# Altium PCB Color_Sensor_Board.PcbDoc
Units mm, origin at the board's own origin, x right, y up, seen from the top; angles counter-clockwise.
Board outline 30 x 30 mm, 2 copper layers (Top Layer, Bottom Layer), stack 1.586 mm thick; 46 components, 24 nets, 122 pads, 55 vias.
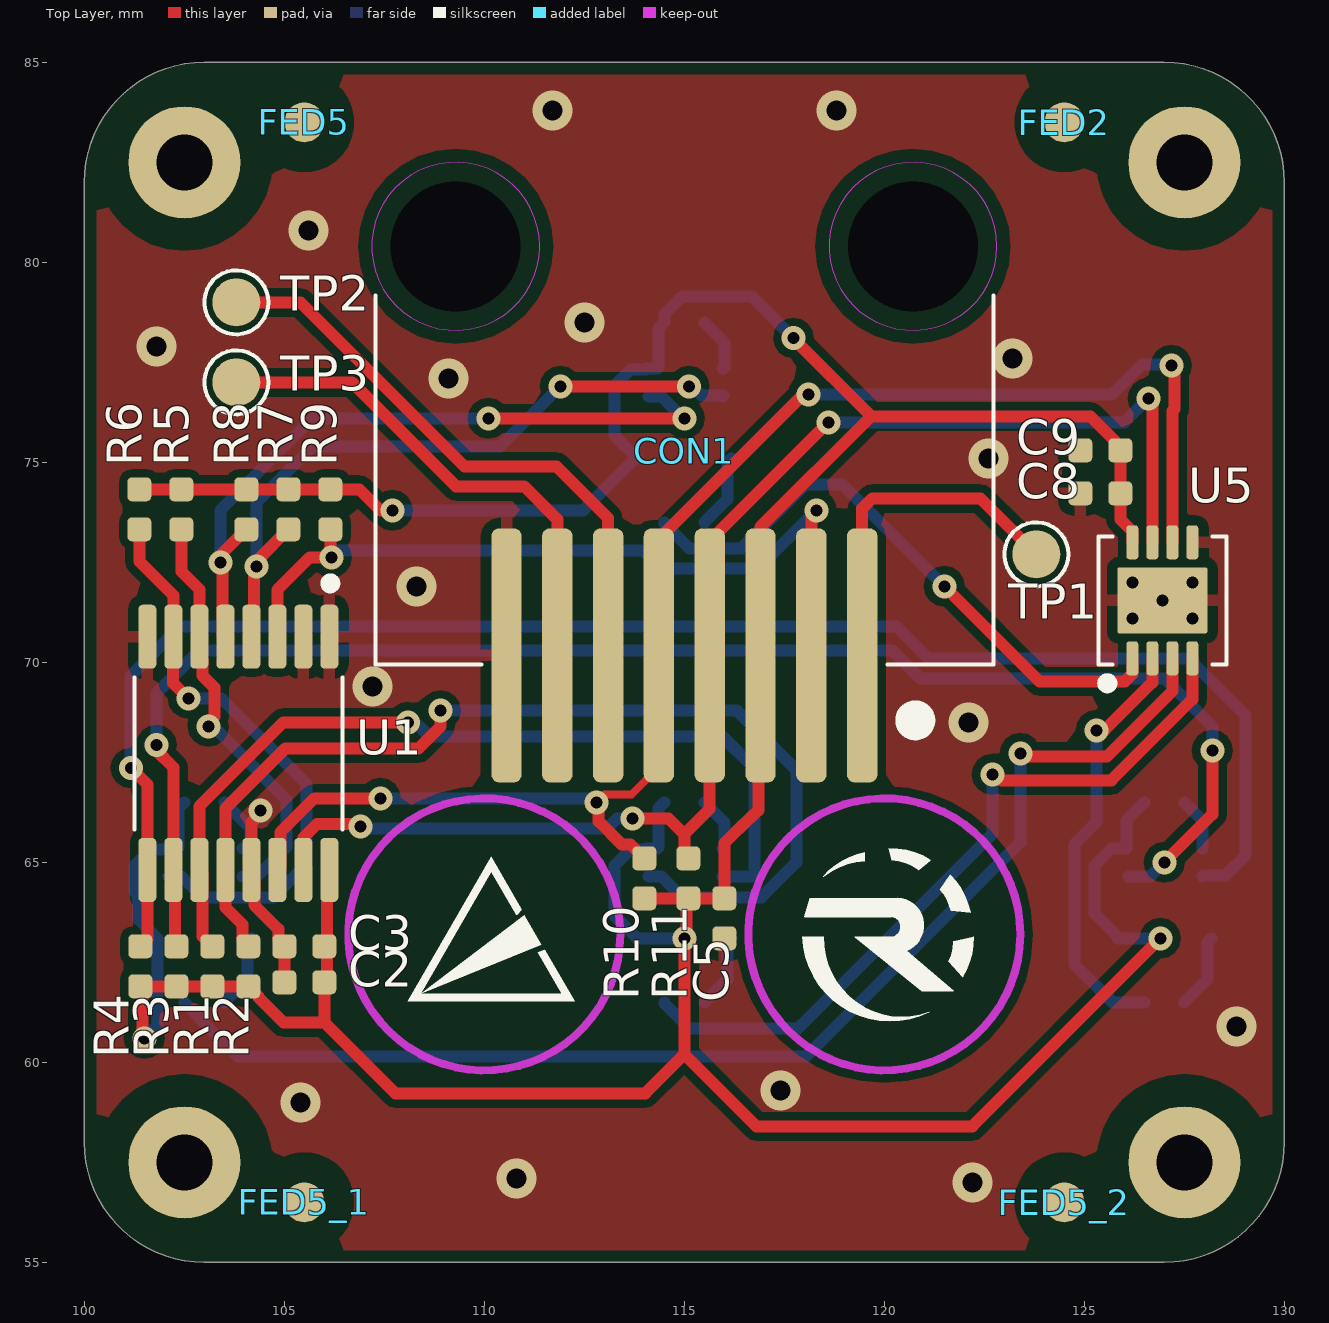
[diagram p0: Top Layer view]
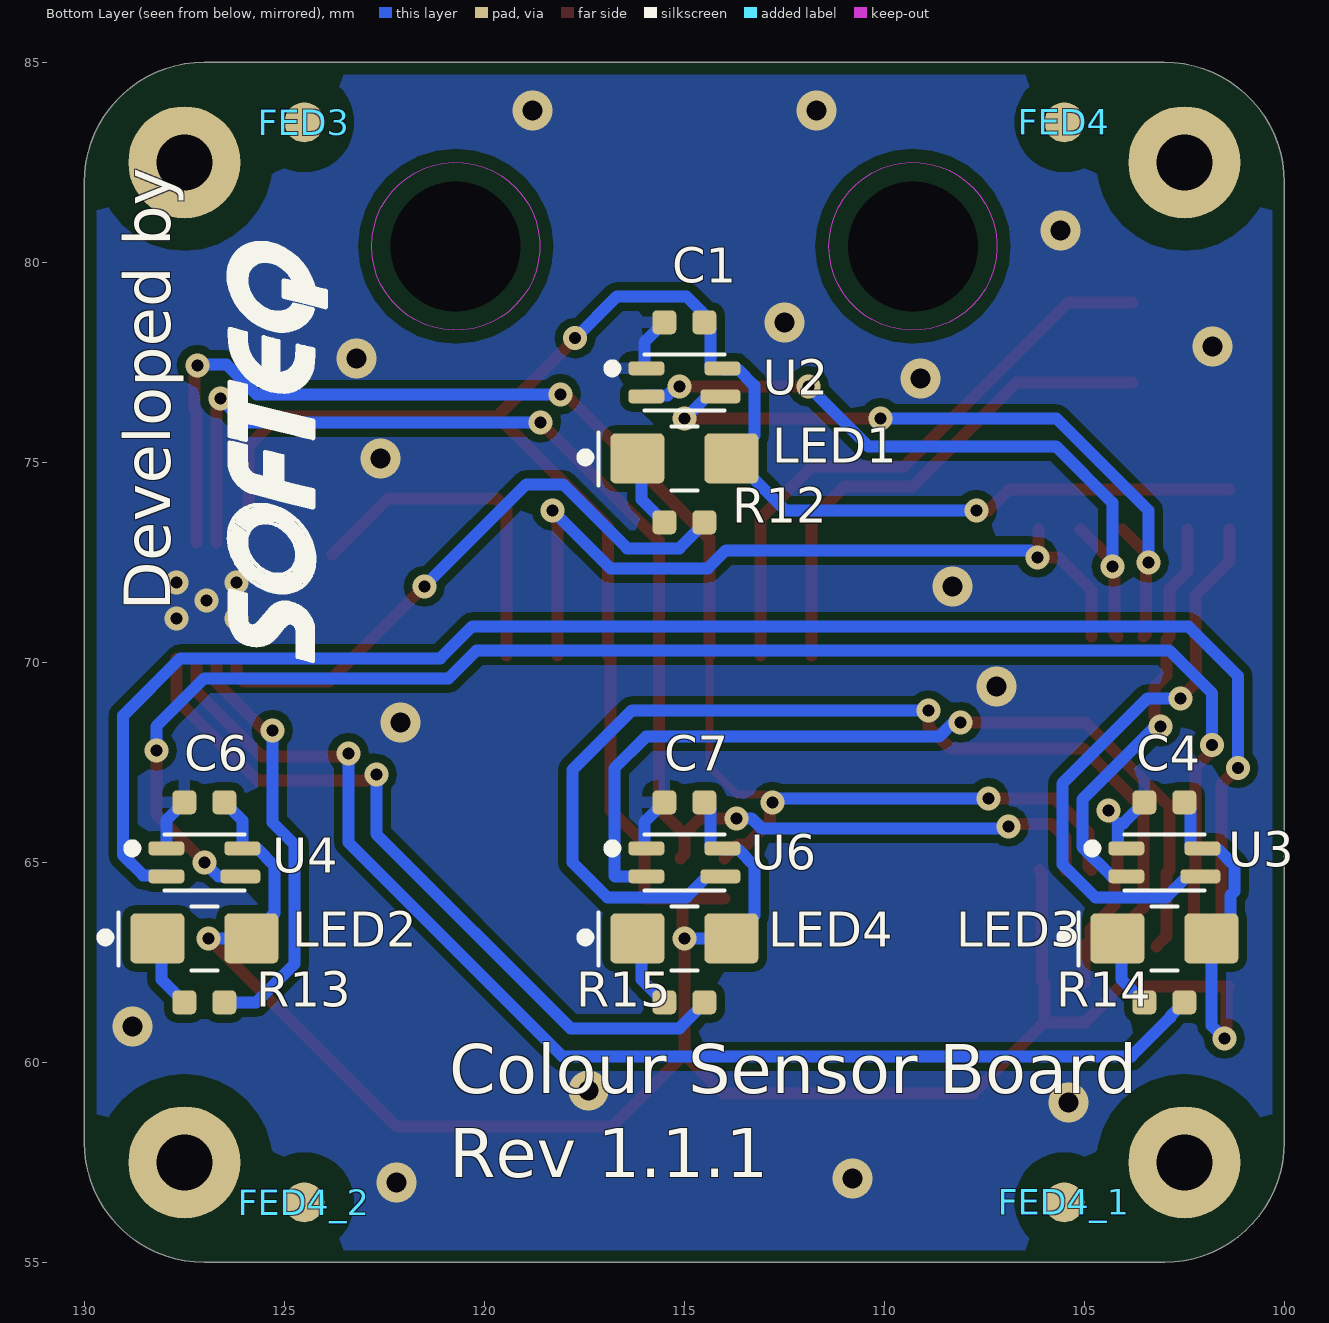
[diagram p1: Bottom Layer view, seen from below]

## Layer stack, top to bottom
Top Solder: solder mask 0.0254, SM-002, Dk 4
Top Layer: signal copper 0.043
Dielectric 1: dielectric 1.5, FR-4, Dk 4.8
Bottom Layer: signal copper 0.043
Bottom Solder: solder mask 0.0254, SM-002, Dk 4

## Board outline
100,58 100,82 cw(c103,82) 103,85 127,85 cw(c127,82) 130,82 130,58 cw(c127,58) 127,55 103,55 cw(c103,58)

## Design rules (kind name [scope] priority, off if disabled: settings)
BoardOutlineClearance [All] p1: gap=0.3 ignorepadtopadclearanceinfootprint=FALSE
Clearance [All] p1: gap=0.2 ignorepadtopadclearanceinfootprint=FALSE except(0.8: THPad-Fill THPad-Poly THPad-Region)
HoleSize [All] p1: absolutevalues=TRUE maxlimit=5 minlimit=0.025 maxpercent=80.000 minpercent=20.000
MinimumSolderMaskSliver [All] p1: minsoldermaskwidth=0.1
PolygonConnect [All] p1: thpad.connectstyle=Relief thpad.reliefconductorwidth=0.3 thpad.reliefentries=4 thpad.polygonreliefangle="90 Angle" thpad.airgapwidth=0.25 smdpad.connectstyle=Relief smdpad.reliefconductorwidth=0.3 smdpad.reliefentries=4 smdpad.polygonreliefangle="90 Angle" smdpad.airgapwidth=0.25 via.connectstyle=Direct via.reliefconductorwidth=0.254 via.reliefentries=4 via.polygonreliefangle="90 Angle" via.airgapwidth=0.254
RoutingVias [All] p1: holewidth=0.3 width=0.6 viastyle="Through Hole" minholewidth=0.3 minwidth=0.6 maxholewidth=0.711 maxwidth=1.27
SilkToSilkClearance [All] p1: silktosilkclearance=0
SilkToSolderMaskClearance [IsPad] p1: minsilkscreentomaskgap=0.1 clearancetoexposedcopper=TRUE
SolderMaskExpansion [All] p1: expansion=0.102
Width [All] p1: maxlimit=2 minlimit=0.2 preferedwidth=0.3
26 further rules are at their usual default settings.

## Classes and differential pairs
component class 1_Circuit: C1 C2 C3 C4 C5 C6 C7 C8 C9 CON1 LED1 LED2 LED3 LED4 R1 R2 R3 R4 R5 R6 R7 R8 R9 R10 R11 R12 R13 R14 R15 TP1 TP2 TP3 U1 U2 U3 U4 U5 U6

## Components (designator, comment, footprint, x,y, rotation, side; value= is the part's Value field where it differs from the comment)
C1 "CC0402KRX7R7BB104" C_0402 115,78.5 r180 bottom value=100n
C2 "CC0402KRX5R7BB105" C_0402 105.5,62 r0 top value=1u
C3 "CC0402KRX7R7BB104" C_0402 105.5,62.9 r0 top value=100n
C4 "CC0402KRX7R7BB104" C_0402 103,66.5 r180 bottom value=100n
C5 "C0402C106M9PAC7867" C_0402 116,63.6 r90 top value=10u
C6 "CC0402KRX7R7BB104" C_0402 127,66.5 r180 bottom value=100n
C7 "CC0402KRX7R7BB104" C_0402 115,66.5 r180 bottom value=100n
C8 "CC0402KRX5R7BB105" C_0402 125.4,74.225 r0 top value=1u
C9 "CC0402KRX7R7BB104" C_0402 125.4,75.3 r0 top value=100n
CON1 "0955016890" MOLEX_955016890 115,70.175 r180 top locked
FED2 "FEDUCIAL_1MM" FEDUCIAL 124.5,83.5 r0 top
FED3 "FEDUCIAL_1MM" FEDUCIAL 124.5,83.5 r180 bottom
FED4 "FEDUCIAL_1MM" FEDUCIAL 105.5,83.5 r180 bottom
FED4_1 "FEDUCIAL_1MM" FEDUCIAL 105.5,56.5 r180 bottom
FED4_2 "FEDUCIAL_1MM" FEDUCIAL 124.5,56.5 r180 bottom
FED5 "FEDUCIAL_1MM" FEDUCIAL 105.5,83.5 r0 top
FED5_1 "FEDUCIAL_1MM" FEDUCIAL 105.5,56.5 r0 top
FED5_2 "FEDUCIAL_1MM" FEDUCIAL 124.5,56.5 r0 top
LED1 "LTW-M140SZS40" Lite-On_LTW-M140SZS40 115,75.1 r180 bottom
LED2 "LTW-M140SZS40" Lite-On_LTW-M140SZS40 127,63.1 r180 bottom
LED3 "LTW-M140SZS40" Lite-On_LTW-M140SZS40 103,63.1 r180 bottom
LED4 "LTW-M140SZS40" Lite-On_LTW-M140SZS40 115,63.1 r180 bottom
R1 "RC0402FR-074K7L" R_0402 103.2,62.4 r270 top value=4.7K
R2 "RC0402FR-074K7L" R_0402 104.1,62.4 r270 top value=4.7K
R3 "RC0402FR-074K7L" R_0402 101.4,62.4 r270 top value=4.7K
R4 "RC0402FR-074K7L" R_0402 102.3,62.4 r270 top value=4.7K
R5 "RC0402FR-074K7L" R_0402 102.425,73.825 r90 top value=4.7K
R6 "RC0402FR-074K7L" R_0402 101.375,73.825 r90 top value=4.7K
R7 "RC0402FR-074K7L" R_0402 105.1,73.825 r90 top value=4.7K
R8 "RC0402FR-074K7L" R_0402 104.05,73.825 r90 top value=4.7K
R9 "RC0402FR-07100KL" R_0402 106.15,73.825 r90 top value=100K
R10 "RC0402FR-074K7L" R_0402 114,64.6 r270 top value=4.7K
R11 "RC0402FR-074K7L" R_0402 115.1,64.6 r270 top value=4.7K
R12 "RC0402FR-0715RL" R_0402 115,73.5 r0 bottom value=15
R13 "RC0402FR-0715RL" R_0402 127,61.5 r0 bottom value=15
R14 "RC0402FR-0715RL" R_0402 103,61.5 r0 bottom value=15
R15 "RC0402FR-0715RL" R_0402 115,61.5 r0 bottom value=15
TP1 "SolderPoint_1.2" SSP_1.2 123.8,72.7 r0 top
TP2 "SolderPoint_1.2" SSP_1.2 103.8,79 r90 top
TP3 "SolderPoint_1.2" SSP_1.2 103.8,77 r90 top
U1 "PCA9546APW" TSSOP-16[8-8]_0.45_0.65_4.4x5x1.1 103.85,67.725 r270 top
U2 "VEML3328" Vishay_VEML3328 115,77 r180 bottom
U3 "VEML3328" Vishay_VEML3328 103,65 r180 bottom
U4 "VEML3328" Vishay_VEML3328 127,65 r180 bottom locked
U5 "PCA9633TK,118" SON-8[4-4]_0.3_0.5_3x3x0.8_EP[1.65x2.25] 126.95,71.55 r90 top
U6 "VEML3328" Vishay_VEML3328 115,65 r180 bottom locked

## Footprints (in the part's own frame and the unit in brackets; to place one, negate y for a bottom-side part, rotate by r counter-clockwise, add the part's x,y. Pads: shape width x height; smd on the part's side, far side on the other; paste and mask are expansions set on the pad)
C_0402 [mm]
  rrect40% 0.6x0.6 smd paste-0.025 mask+0.05: 1(-0.5,0) 2(0.5,0)
  body extent -0.5,-0.25 0.5,0.25, height 0.55
FEDUCIAL [mm]
  round 1 smd paste-1 mask+0.5: FED(0,0)
  Top Layer pour cut-out: 0,1.25 0.478,1.155 0.884,0.884 1.155,0.478 1.25,0 1.25,0 1.155,-0.478 0.884,-0.884 0.478,-1.155 0,-1.25 0,-1.25 -0.478,-1.155 -0.884,-0.884 -1.155,-0.478 -1.25,0 -1.25,0 -1.155,0.478 -0.884,0.884 -0.478,1.155 0,1.25
Lite-On_LTW-M140SZS40 [mm]
  rrect20% 1.35x1.25 smd paste-0.025 mask+0.05: A(1.175,0) C(-1.175,0)
  silkscreen extent -2.57,-0.8 0.32,0.8, body extent -1.5,-0.7 1.5,0.7, height 1.2
MOLEX_955016890 [mm]
  rrect50% 0.76x6.35 smd paste-0.025 mask+0.05: 1(-4.445,0) 2(-3.175,0) 3(-1.905,0) 4(-0.635,0) 5(0.635,0) 6(1.905,0) 7(3.175,0) 8(4.445,0)
  round 0 hole 3.25 unplated mask+0.3: SH(-5.715,-10.225) SH(5.715,-10.225)
  Keep-Out Layer circle w0.025: c5.715,-10.225 r2.1
  Keep-Out Layer circle w0.025: c-5.715,-10.225 r2.1
  silkscreen extent -7.73,-9 7.73,1.87, body extent -7.62,-18.02 7.62,2.53, height 11.5
R_0402 [mm]
  rrect40% 0.6x0.6 smd paste-0.025 mask+0.05: 1(-0.5,0) 2(0.5,0)
  body extent -0.57,-0.27 0.58,0.28, height 0.4
SON-8[4-4]_0.3_0.5_3x3x0.8_EP[1.65x2.25] [mm] "SON, 8-Leads, Body 3.00x3.00mm, Pitch 0.50mm, IPC Medium Density"
  rrect50% 0.85x0.3 smd paste-0.025 mask+0.05: 1(-1.45,0.75) 2(-1.45,0.25) 3(-1.45,-0.25) 4(-1.45,-0.75) 5(1.45,-0.75) 6(1.45,-0.25) 7(1.45,0.25) 8(1.45,0.75)
  rrect5% 1.65x2.25 smd paste-2 mask+0.05: EP(0,0)
  silkscreen extent -2.33,-1.6 1.6,1.62, body extent -1.5,-1.5 1.5,1.5, height 1
SSP_1.2 [mm]
  round 1.2 smd paste-1.5 mask+0.05: 1(0,0)
  silkscreen extent -0.8,-0.8 0.8,0.8
TSSOP-16[8-8]_0.45_0.65_4.4x5x1.1 [mm]
  rrect49% 1.6x0.45 smd paste-0.025 mask+0.05: 1(-2.915,2.275) 2(-2.915,1.625) 3(-2.915,0.975) 4(-2.915,0.325) 5(-2.915,-0.325) 6(-2.915,-0.975) 7(-2.915,-1.625) 8(-2.915,-2.275) 9(2.915,-2.275) 10(2.915,-1.625) 11(2.915,-0.975) 12(2.915,-0.325) 13(2.915,0.325) 14(2.915,0.975) 15(2.915,1.625) 16(2.915,2.275)
  silkscreen extent -4.37,-2.6 1.9,2.6, body extent -3.2,-2.5 3.2,2.5, height 1.1
Vishay_VEML3328 [mm]
  rrect50% 0.9x0.35 smd paste-0.025 mask+0.05: 1(-0.95,0.35) 2(-0.95,-0.35) 4(0.95,0.35)
  rrect50% 1x0.35 smd paste-0.025 mask+0.05: 3(0.9,-0.35)
  silkscreen extent -1.9,-0.7 1,0.7, body extent -1,-0.62 1,0.63, height 1.01

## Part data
C1 C3 C4 C6 C7 C9: "Capacitor, 100nF, 16V, X7R, 10%, -55/+125,0402", Manufacturer=Yageo
C2 C8: "Capacitor, 1uF, 16V, X5R, 10%, -55/+85, 0402", Manufacturer=Yageo
C5: "Capacitor, 10uF, 6.3V, 20%, X5R, -55/+85 0402", Manufacturer=Kemet
CON1: "Conn, RJ-45, Unshielded, P-1.27mm, RA, -40/+85, SMD", Manufacturer=Molex
FED2 FED3 FED4 FED4_1 FED4_2 FED5 FED5_1 FED5_2: Manufacturer=-
LED1 LED2 LED3 LED4: "Diode, LED, White, 20mA, 3.2V, -30/+85, 3.0x1.4x1.2mm", Manufacturer=Lite-On
R1 R2 R3 R4 R5 R6 R7 R8 R10 R11: "Resistor, 4.7K, 1%, 0.063W, -55/+155, 0402", Manufacturer=Yageo
R9: "Resistor, 100K, 1%, 0.063W, -55/+155, 0402", Manufacturer=Yageo
R12 R13 R14 R15: "Resistor, 15, 1%, 0.0625W, -55/+155, 0402", Manufacturer=Yageo
TP1 TP2 TP3: library part SolderPoint_SMD_1.2, "Solder Point, 1.2mm, SMD"
U1: "IC, I2C/SMBus Switch, 4Ch, 400kHz, -40/+85, TSSOP-16", Manufacturer=NXP
U2 U3 U4 U6: "IC, Color Sensor, RGBCIR, I2C/SMBus, 2.6-3.6V, -40/+85, SMD", Manufacturer=Vishay
U5: "IC, LED Driver, 4Ch, 2.3-5.5V, 25mA/Ch, 100mAmax, -40/+85, HVSON-8", Manufacturer=NXP

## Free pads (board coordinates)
  round 2.8 hole 1.4: 2(102.5,57.5) 2(127.5,57.5)
  round 2.8 hole 1.4 mask+0.05: 2(102.5,82.5) 2(127.5,82.5)

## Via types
v1: diameter 0.6, hole 0.3, Top Layer to Bottom Layer, tented both sides, 34 vias
v2: diameter 1, hole 0.5, Top Layer to Bottom Layer, tented both sides, 16 vias
v3: diameter 0.6, hole 0.3, Top Layer to Bottom Layer, tented bottom, 5 vias

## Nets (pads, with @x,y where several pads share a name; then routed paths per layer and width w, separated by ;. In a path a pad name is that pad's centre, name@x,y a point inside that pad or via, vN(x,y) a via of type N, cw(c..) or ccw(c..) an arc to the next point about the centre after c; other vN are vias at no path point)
GND: C1.1 C2.1 C3.1 C4.1 C5.1 C6.1 C7.1 C8.1 C9.1 CON1.8 U1.1 U1.2 U1.8 U1.13 U2.1 U3.1 U4.1 U5.5 U5.EP U6.1 | length 10.5
  Top Layer w0.3: v1(104.4,66.3) 104.4,66.219 104.175,65.994 U1.13 104.25,64.735 104.25,63.93 104.85,63.33 104.85,63.05 C3.1 C2.1
  Bottom Layer w0.3: C4.1 104.025,65.975 104.156,65.975 104.156,65.375 104.131,65.35 U3.1 ; C7.1 115.998,66.002 115.998,65.375 115.973,65.35 U6.1 ; C1.1 115.998,78.002 115.998,77.375 115.973,77.35 U2.1 ; C6.1 127.95,66.05 U4.1
  other v2: 122.2,57 110.8,57.1 105.4,59 117.4,59.3 128.8,60.9 122.1,68.5 107.2,69.4 108.3,71.9 122.6,75.1 109.1,77.1 123.2,77.6 101.8,77.9 112.5,78.5 105.6,80.8 111.7,83.8 118.8,83.8
  other v3: 126.2,71.1 127.7,71.1 126.95,71.55 126.2,72 127.7,72
I2C_SCL_CS: R2.1 U1.12 U6.3 | length 26.4
  Top Layer w0.3: R2.1 103.95,63.05 103.95,63.45 103.525,63.875 U1.12 103.525,66.344 105.031,67.85 108.359,67.85 108.9,68.39 v1(108.9,68.795)
  Bottom Layer w0.3: v1(108.9,68.795) 116.312,68.795 117.8,67.307 117.8,65 116.925,64.125 114.95,64.125 114.425,64.65 U6.3
I2C_SCL_FS: R8.1 U1.5 U2.3 | length 18
  Top Layer w0.3: U1.5 103.457,70.708 103.457,72.443 v1(103.4,72.5) 103.4,72.675 R8.1 ; v1(110.1,76.1) v1(115,76.1)
  Bottom Layer w0.3: v1(103.4,72.5) 103.4,73.8 105.7,76.1 v1(110.1,76.1) ; U2.3 114.425,76.65 114.975,76.1 v1(115,76.1)
I2C_SCL_LS: R6.1 U1.7 U3.3 | length 14.6
  Top Layer w0.3: R6.1 101.375,72.525 102.225,71.675 U1.7 102.212,70.628 102.212,69.487 v1(102.6,69.1)
  Bottom Layer w0.3: U3.3 102.425,64.65 102.95,64.125 104.725,64.125 105.55,64.95 105.55,66.969 103.419,69.1 v1(102.6,69.1)
I2C_SCL_MAIN: CON1.5 R10.1 U1.14 U5.6 | length 38
  Top Layer w0.2: v1(112.8,66.5) 113,66.7 113.685,66.7 114.365,67.38 CON1.5
  Top Layer w0.3: U1.14 104.9,64.885 104.9,65.747 105.752,66.6 v1(107.4,66.6) ; v1(112.8,66.5) 112.857,66.443 112.857,66.023 113.431,65.45 113.65,65.45 R10.1 ; CON1.5 114.365,73.084 117.981,76.7 v1(118.1,76.7) ; v1(127.175,77.425) 127.25,77.35 127.25,76.331 127.2,76.281 U5.6
  Bottom Layer w0.3: v1(107.4,66.6) 112.7,66.6 v1(112.8,66.5) ; v1(118.1,76.7) 125.7,76.7 126.45,77.45 127.15,77.45 v1(127.175,77.425)
I2C_SCL_RS: R4.1 U1.10 U4.3 | length 39.1
  Top Layer w0.3: v1(101.805,67.933) 101.805,67.795 102.225,67.375 U1.10 102.262,64.772 102.262,62.938 R4.1 ; v1(127,65) 128.2,66.2 v1(128.2,67.8)
  Bottom Layer w0.3: v1(101.805,67.933) 101.805,69.224 102.881,70.3 120.193,70.3 120.893,69.6 127,69.6 128.2,68.4 v1(128.2,67.8) ; U4.3 126.65,64.65 v1(127,65)
I2C_SDA_CS: R1.1 U1.11 U6.2 | length 22.3
  Top Layer w0.3: R1.1 102.95,63.15 102.95,64.735 U1.11 102.875,66.401 104.974,68.5 v1(108.09,68.5)
  Bottom Layer w0.3: v1(108.09,68.5) 108.276,68.5 108.631,68.145 115.955,68.145 116.75,67.35 116.75,64.664 116.736,64.65 U6.2
I2C_SDA_FS: R7.1 U1.4 U2.2 | length 17.8
  Top Layer w0.3: U1.4 104.242,70.707 104.242,72.342 v1(104.3,72.4) 104.357,72.457 104.357,72.582 R7.1 ; v1(111.9,76.9) v1(115.119,76.9)
  Bottom Layer w0.3: v1(104.3,72.4) 104.3,73.993 105.707,75.4 110.4,75.4 v1(111.9,76.9) ; v1@115.194,76.825 v1(115.119,76.9) 115.2,76.9 115.425,76.675 115.925,76.675 U2.2 U2.2@115.975,76.675
I2C_SDA_LS: R5.1 U1.6 U3.2 | length 10.6
  Top Layer w0.3: R5.1 102.425,72.275 102.875,71.825 U1.6 102.943,70.572 102.943,70.05 102.95,70.05 102.95,69.669 103.25,69.369 103.25,68.65 v1@103.11,68.51 ; v1(103.1,68.4) v1@103.1,68.5 ; v1@103.1,68.5 103.1,68.519 v1@103.11,68.51 ; v1@103.1,68.5 v1@103.11,68.51
  Bottom Layer w0.3: v1@103.16,68.46 105.05,66.569 105.05,65.381 104.319,64.65 U3.2
I2C_SDA_MAIN: CON1.4 R11.1 U1.15 U5.7 | length 35.1
  Top Layer w0.3: U1.15 105.475,65.615 105.82,65.96 106.43,65.96 106.433,65.957 106.843,65.957 v1(106.9,65.9) ; v1(113.7,66.1) 114.6,66.1 115,65.7 ; R11.1 115,65.2 115,65.7 ; v1(118.6,76) 115.635,73.035 CON1.4 115.635,66.335 115,65.7 ; v1(126.6,76.6) 126.7,76.5 U5.7
  Bottom Layer w0.3: v1(106.9,65.9) 106.95,65.85 113.069,65.85 113.319,66.1 v1(113.7,66.1) ; v1(118.6,76) 126,76 v1(126.6,76.6)
I2C_SDA_RS: R3.1 U1.9 U4.2 | length 41.1
  Top Layer w0.3: v1(101.164,67.358) 101.575,66.948 U1.9 101.575,63.075 R3.1
  Bottom Layer w0.3: v1(101.164,67.358) 101.155,67.368 101.155,69.655 102.4,70.9 120.3,70.9 121.1,70.1 127.6,70.1 129.034,68.666 129.034,65.181 128.528,64.675 127.975,64.675 U4.2
NetCON1_1: CON1.1 TP1.1 | length 8.7
  Top Layer w0.3: CON1.1 119.445,73.845 119.7,74.1 122.4,74.1 TP1.1
NetCON1_6: CON1.6 TP2.1 | length 15
  Top Layer w0.3: TP2.1 105.4,79 109.5,74.9 111.8,74.9 113.095,73.605 CON1.6
NetCON1_7: CON1.7 TP3.1 | length 12.8
  Top Layer w0.3: TP3.1 106.693,77 109.293,74.4 110.995,74.4 111.825,73.57 CON1.7
NetLED1_C: LED1.C R12.2 | length 1.9
  Bottom Layer w0.3: R12.2 116.074,74.074 116.074,74.999 LED1.C
NetLED2_C: LED2.C R13.2 | length 1.9
  Bottom Layer w0.3: R13.2 128.074,62.074 128.074,62.999 LED2.C
NetLED3_C: LED3.C R14.2 | length 1.9
  Bottom Layer w0.3: R14.2 104.074,62.074 104.074,62.999 LED3.C
NetLED4_C: LED4.C R15.2 | length 1.9
  Bottom Layer w0.3: R15.2 116.074,62.074 116.074,62.999 LED4.C
NetR12_1: R12.1 U5.1 | length 15.2
  Top Layer w0.3: v1(121.5,71.9) 123.875,69.525 126.018,69.525 126.2,69.707 U5.1
  Bottom Layer w0.3: R12.1 114.5,73.475 115.125,72.85 116.431,72.85 118.031,74.45 118.95,74.45 v1(121.5,71.9)
NetR13_1: R13.1 U5.2 | length 10.7
  Top Layer w0.3: v1(125.3,68.3) 125.5,68.3 126.7,69.5 U5.2
  Bottom Layer w0.3: v1(125.3,68.3) 125.3,66 124.75,65.45 124.75,62.453 125.703,61.5 R13.1
NetR14_1: R14.1 U5.3 | length 31.2
  Top Layer w0.3: v1(123.4,67.725) 123.475,67.65 125.569,67.65 127.2,69.281 U5.3
  Bottom Layer w0.3: R14.1 102.85,61.15 102.85,61.125 103.825,60.15 118.05,60.15 123.4,65.5 v1(123.4,67.725)
NetR15_1: R15.1 U5.4 | length 18.9
  Top Layer w0.3: v1(122.7,67.2) 122.781,67.2 122.931,67.05 125.676,67.05 127.7,69.074 U5.4
  Bottom Layer w0.3: R15.1 114.5,61.475 115.125,60.85 117.845,60.85 122.7,65.705 v1(122.7,67.2)
RESET: CON1.2 R9.1 U1.3 | length 20.2
  Top Layer w0.3: U1.3 104.825,71.813 105.637,72.625 v1(106.175,72.625) 106.15,72.65 R9.1 ; CON1.2 118.175,73.675 v1(118.3,73.8)
  Bottom Layer w0.3: v1(106.175,72.625) 106.35,72.8 113.964,72.8 114.414,72.35 116.85,72.35 v1(118.3,73.8)
VDD_3V3: C1.2 C2.2 C3.2 C4.2 C5.2 C6.2 C7.2 C8.2 C9.2 CON1.3 LED1.A LED2.A LED3.A LED4.A R1.2 R2.2 R3.2 R4.2 R5.2 R6.2 R7.2 R8.2 R9.2 R10.2 R11.2 U1.16 U2.4 U3.4 U4.4 U5.8 U6.4 | length 106.4
  Top Layer w0.3: R6.2 R5.2 R7.2 R9.2 106.875,74.325 107.4,73.8 v1(107.7,73.8) ; v1(101.5,60.6) 101.45,60.65 101.45,61.85 R3.2 R4.2 R1.2 R2.2 104.35,61.65 104.35,61.625 104.975,61 106,61 ; U1.16 106.062,64.748 106.062,62.062 C2.2 106,61 ; R10.2 R11.2 ; v1(117.729,78.105) 117.729,78.09 119.669,76.15 ; U5.8 126.2,73.275 125.9,73.575 C8.2 C9.2 125.9,75.4 125.15,76.15 119.669,76.15 ; v1(126.9,63.1) 122.2,58.4 116.8,58.4 115,60.2 ; 106,61 107.775,59.225 114.025,59.225 115,60.2 ; 115,60.2 v1(115,63.1) 115.05,63.15 115.05,64.05 R11.2 ; R11.2 C5.2 116,65.475 116.388,65.862 116.85,66.3 116.85,70.12 CON1.3 116.905,73.386 119.669,76.15
  Bottom Layer w0.3: v1(101.5,60.6) 101.825,60.925 LED3.A 101.822,63.1 101.347,63.575 101.347,64.175 101.25,64.272 101.25,64.919 101.656,65.325 102.025,65.325 U3.4 102.325,65.35 102.35,65.375 102.35,66.35 C4.2 ; v1(107.7,73.8) 112.475,73.8 113.775,75.1 LED1.A@113.822,75.1 ; LED1.A LED1.A@113.822,75.1 ; C7.2 114.35,66.35 114.35,65.375 114.325,65.35 U6.4 114.025,65.325 113.656,65.325 113.25,64.919 113.25,63.672 113.822,63.1 LED4.A v1(115,63.1) ; v1(117.729,78.105) 116.684,79.15 114.95,79.15 114.5,78.7 C1.2 114.35,78.35 114.35,77.375 114.325,77.35 U2.4 114.025,77.325 113.656,77.325 113.25,76.919 113.25,75.672 LED1.A@113.822,75.1 ; LED2.A LED2.A@125.875,63.1 ; C6.2 126.05,66.05 U4.4 125.681,65.35 125.25,64.919 125.25,63.725 LED2.A@125.875,63.1 ; v1(126.9,63.1) LED2.A@125.875,63.1
pads on no net: CON1.SH FED2.FED FED3.FED FED4.FED FED4_1.FED FED4_2.FED FED5.FED FED5_1.FED FED5_2.FED

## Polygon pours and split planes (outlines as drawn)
GND on Bottom Layer "GND_L02_P000" (solid, remove dead copper, pour order 0): 99.425,71.725 99.425,77.737 cw(c109.571,79.947) 100,83.975 cw(c105.362,79.779) 104.537,86.537 126.65,86.175 cw(c126.448,82.669) 129.075,85 130.4,82 cw(c125.105,79.7) 130.475,77.581 130.475,57.352 cw(c127.936,57.352) 129.731,55.556 129.075,54.9 cw(c127.989,55.986) 127.989,54.45 102.377,54.45 cw(c102.377,56.99) 100.581,55.194 100,55.775 cw(c101.449,57.224) 99.4,57.224 99.4,60.775
GND on Top Layer "GND_L01_P001" (solid, remove dead copper, pour order 1): 99.425,71.775 99.4,82.425 cw(c101.827,82.973) 99.723,84.302 100,84.65 cw(c102.546,82.343) 102.377,85.775 126.025,85.975 cw(c126.42,82.462) 128.625,85.225 129.425,84.65 cw(c121.479,79.873) 130.475,77.631 130.475,57.402 cw(c127.935,57.402) 129.731,55.606 129.075,54.95 cw(c127.989,56.036) 127.989,54.5 102.377,54.5 cw(c102.377,57.04) 100.581,55.244 100,55.825 cw(c101.449,57.274) 99.4,57.274 99.4,60.825

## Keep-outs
Top Layer:
  circle w0.2: c120,63.2 r3.4
  circle w0.2: c110,63.2 r3.4
  region: 107.8,65.9

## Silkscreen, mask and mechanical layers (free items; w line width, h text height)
Top Overlay:
  region: 108.09,61.525 110.175,65.137 110.94,63.812 110.82,63.692 110.796,63.692 110.175,64.767 108.41,61.71 111.428,62.94 111.002,63.677 111.428,62.94 111.002,63.677 108.411,61.711 111.94,61.711 111.337,62.755 111.514,62.818 112.26,61.525
  region: 118.151,64.096 118.01,63.635 120.169,63.635 cw(c120.169,63.387) 120.169,63.139 119.267,63.139 120.938,61.787 121.722,61.787 120.546,62.792 ccw(c120.323,63.425) 120.323,64.096
  region: 117.942,63.139 ccw(c120.15,63.247) 121.119,61.26 cw(c120.439,63.107) 118.47,63.139
  region: 121.65,64.672 121.403,64.313 cw(c120.569,63.557) 121.668,63.801 122.157,63.751 ccw(c120.471,63.422)
  region: 120.116,65.337 120.184,65.057 cw(c120.056,63.613) 120.86,64.819 121.146,65.057 ccw(c120.184,63.551)
  region: 121.741,63.021 122.234,63.139 cw(c120.405,63.095) 121.961,62.133 121.612,62.524 ccw(c120.614,63.048)
  region: 119.511,65.245 ccw(c119.899,63.387) 118.474,64.641 cw(c119.644,63.084) 119.511,65.027
  lines w0.013: 117.942,63.139 ccw(c120.15,63.247) 121.119,61.26 cw(c120.439,63.107) 118.47,63.139 117.942,63.139 ; 118.01,63.635 118.151,64.096 120.323,64.096 cw(c120.323,63.425) 120.546,62.792 121.722,61.787 120.938,61.787 119.267,63.139 120.169,63.139 ccw(c120.169,63.387) 120.169,63.635 118.01,63.635 ; 118.474,64.641 cw(c119.644,63.084) 119.511,65.027 119.511,65.245 ccw(c119.899,63.387) 118.474,64.641 ; 120.116,65.337 cw(c120.184,63.551) 121.146,65.057 120.86,64.819 ccw(c120.056,63.613) 120.184,65.057 120.116,65.337 ; 121.403,64.313 cw(c120.569,63.557) 121.668,63.801 122.157,63.751 ccw(c120.471,63.422) 121.65,64.672 121.403,64.313 ; 121.612,62.524 ccw(c120.614,63.048) 121.741,63.021 122.234,63.139 cw(c120.405,63.095) 121.961,62.133 121.612,62.524
Bottom Overlay:
  drawing of 467 lines, arcs and shapes, not listed
  text "Developed by" at 127.469,71.287 h2 r270
  text "Colour Sensor Board / Rev 1.1.1" at 120.875,56.725 h2.1
Mechanical 1:
  the board outline again, w0.1
Top Assembly:
  lines w0.1: 109.075,80 109.075,88.2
